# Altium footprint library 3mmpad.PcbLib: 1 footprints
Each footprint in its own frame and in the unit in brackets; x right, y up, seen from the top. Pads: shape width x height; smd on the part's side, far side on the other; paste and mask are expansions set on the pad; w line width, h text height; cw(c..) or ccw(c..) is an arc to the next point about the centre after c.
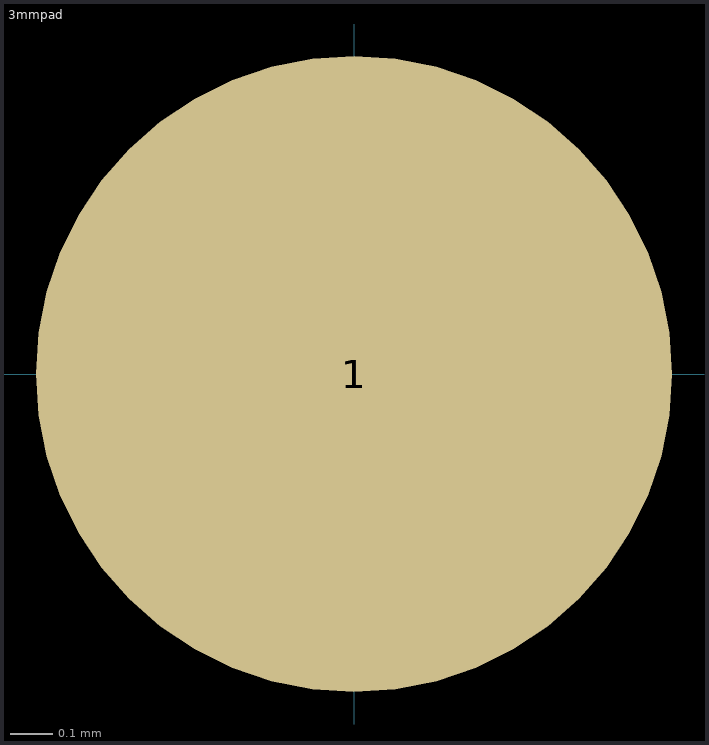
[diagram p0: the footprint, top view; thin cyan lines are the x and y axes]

## 3mmpad [mm]
pads (2):
  round 1.5 smd paste+0 mask+0.102: 1(0,0)
  round 1.5 on Top Solder paste+0 mask+0.102: 1(0,0)
M5 Assembly Top:
  text ".Designator" at -1.8,-0.514 h1.02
